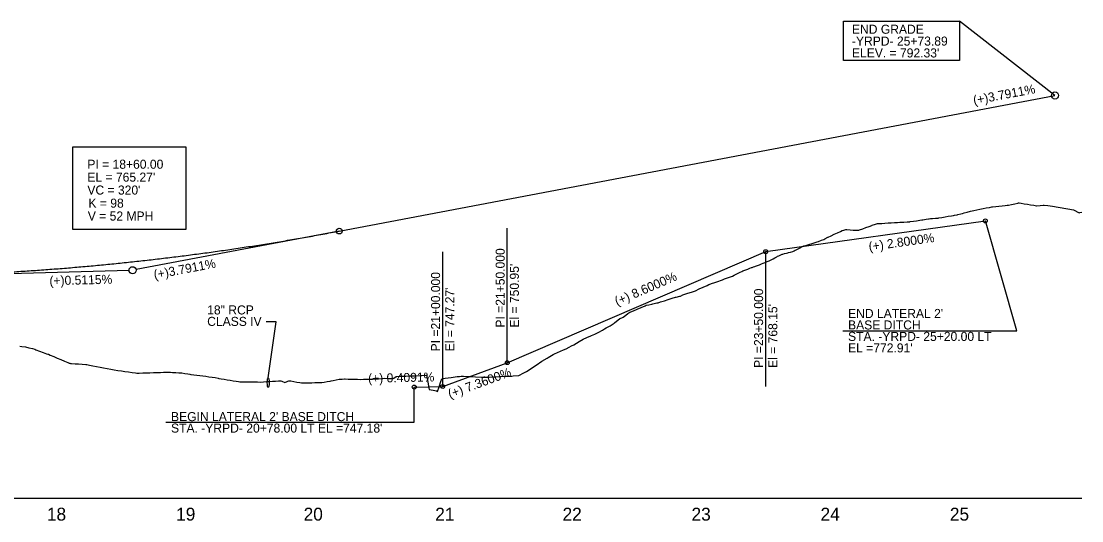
# Model space of a CAD drawing. Extents: x 579185 to 595036, y -53221 to -44640.
# Drawn here: x 580065 to 580886, y -53221 to -52834 of the extents above; entities that cross this region are included whole.
import ezdxf

# ---------------------------------------------------------------- set-up
doc = ezdxf.new("R2010")
doc.units = 0
for name, color, linetype in [('Exist Profile Cell', 7, 'Continuous'), ('Exist Vertical Profile Ground Line', 7, 'Continuous'), ('Exist Vertical Profile Horizontal Axis Label Major', 7, 'Continuous'), ('Prop Grid Mask', 7, 'Continuous'), ('Prop PFL Cross Pipe CELL', 7, 'Continuous'), ('Prop Vertical Profile Curve Label', 7, 'Continuous'), ('Prop Vertical Profile Ditch Grade Left', 7, 'Continuous'), ('Prop Vertical Profile Ditch Grade Left Label', 7, 'Continuous'), ('Prop Vertical Profile Ditch Grade Right Label', 7, 'Continuous'), ('Prop Vertical Profile Grade', 7, 'Continuous'), ('Prop Vertical Profile Grade Label', 7, 'Continuous'), ('Prop VPI Ditch Grade Left Label', 7, 'Continuous'), ('Prop VPI Label', 7, 'Continuous')]:
    doc.layers.add(name, color=color, linetype=linetype)

msp = doc.modelspace()

# ---------------------------------------------------------------- linework, layer by layer
at = {"layer": 'Exist Profile Cell'}
msp.add_line((579291.19, -53202.97), (580885.83, -53202.97), dxfattribs=at)
at = {"layer": 'Exist Vertical Profile Ground Line'}
for points in [[(580816.81, -52977.45), (580819.22, -52977.21), (580821.67, -52976.96), (580824.12, -52976.72), (580826.57, -52976.49), (580828.1, -52976.34), (580829.02, -52976.14), (580831.48, -52975.61), (580833.93, -52975.09), (580836.38, -52974.57), (580836.95, -52974.44), (580837.3, -52974.46), (580838.83, -52974.71), (580841.28, -52975.1), (580843.73, -52975.51), (580846.18, -52975.91), (580848.63, -52976.32), (580850.7, -52976.66), (580851.08, -52976.63), (580853.53, -52976.45), (580855.98, -52976.27), (580856.59, -52976.23), (580859.66, -52976.5), (580863.28, -52977.1), (580879.48, -52979.73), (580883.81, -52982.05), (580884.29, -52982.01), (580885.83, -52981.76)], [(580643.83, -53019.26), (580645.33, -53018.63), (580647.08, -53017.91), (580648.33, -53017.11), (580649.83, -53016.16), (580650.38, -53015.81), (580651.38, -53015.35), (580652.83, -53014.69), (580653.82, -53014.23), (580654.33, -53014.1), (580655.83, -53013.71), (580657.33, -53013.33), (580658.21, -53013.1), (580658.83, -53012.96), (580660.33, -53012.6), (580662.12, -53012.17), (580663.33, -53011.6), (580664.13, -53011.21), (580664.83, -53010.85), (580667.28, -53009.59), (580669.73, -53008.32), (580670.65, -53007.85), (580672.18, -53007.38), (580674.63, -53006.62), (580677.08, -53005.87), (580679.53, -53005.12), (580681.09, -53004.65), (580681.98, -53004.32), (580684.43, -53003.41), (580686.08, -53002.8), (580686.88, -53002.37), (580689.33, -53001.09), (580689.65, -53000.92), (580691.79, -52999.94), (580694.24, -52998.81), (580696.69, -52997.68), (580699.14, -52996.56), (580700.39, -52995.98), (580701.59, -52995.58), (580703.15, -52995.05), (580704.04, -52995.12), (580706.49, -52995.31), (580708.94, -52995.5), (580710.88, -52995.65), (580711.39, -52995.62), (580713.36, -52995.52), (580713.84, -52995.34), (580716.29, -52994.45), (580718.74, -52993.56), (580721.19, -52992.67), (580723.23, -52991.93), (580723.64, -52991.8), (580726.1, -52991.01), (580727.84, -52990.44), (580728.55, -52990.41), (580731, -52990.31), (580733.45, -52990.2), (580735.9, -52990.04), (580738.35, -52989.88), (580740.8, -52989.72), (580743.25, -52989.57), (580744.95, -52989.46), (580745.7, -52989.43), (580748.15, -52989.31), (580750.6, -52989.2), (580752.73, -52989.06), (580753.05, -52989.01), (580755.5, -52988.65), (580757.95, -52988.29), (580760.41, -52987.93), (580762.13, -52987.68), (580762.86, -52987.56), (580765.31, -52987.16), (580767.26, -52986.85), (580767.76, -52986.77), (580768.8, -52986.61), (580770.21, -52986.51), (580772.66, -52986.35), (580774.62, -52986.21), (580775.11, -52986.13), (580777.56, -52985.7), (580780.01, -52985.27), (580782.46, -52984.84), (580784.91, -52984.41), (580786.62, -52984.12), (580787.36, -52983.98), (580789.35, -52983.62), (580789.81, -52983.5), (580792.26, -52982.88), (580793.4, -52982.59), (580794.72, -52982.26), (580797.17, -52981.63), (580799.62, -52981.01), (580802.33, -52980.32), (580804.67, -52979.86), (580806.97, -52979.39), (580809.42, -52978.9), (580811.87, -52978.41), (580814.32, -52977.92), (580816.23, -52977.54), (580816.81, -52977.45)], [(580440.02, -53108.73), (580444.7, -53108.53), (580445.63, -53108.49), (580450.26, -53108), (580454.08, -53105.99), (580456.02, -53104.96), (580463.45, -53100.12), (580468.06, -53097.11), (580471.94, -53094.73), (580472.83, -53094.22), (580476.8, -53091.92), (580477.67, -53091.37), (580484.83, -53088.27), (580486.74, -53087.44), (580489.12, -53086.1), (580490.83, -53085.26), (580492.6, -53084.39), (580496.83, -53081.8), (580499.81, -53079.98), (580502.83, -53078.69), (580505.83, -53077.41), (580506.29, -53077.21), (580508.83, -53076.09), (580512.07, -53074.66), (580514.83, -53072.95), (580516.4, -53071.98), (580517.83, -53071.2), (580520.83, -53069.54), (580523.83, -53067.53), (580524.48, -53067.1), (580526.83, -53065.21), (580528.34, -53063.99), (580529.83, -53063.45), (580530.86, -53063.07), (580532.83, -53061.49), (580534.6, -53060.08), (580535.35, -53059.55), (580535.97, -53059.2), (580536.81, -53058.79), (580538.83, -53057.93), (580541.83, -53056.66), (580544.83, -53055.39), (580547.83, -53054.13), (580548.79, -53053.72), (580550.83, -53053.29), (580552.96, -53052.84), (580553.83, -53052.65), (580556.83, -53051.98), (580557.85, -53051.75), (580559.83, -53051.13), (580562.83, -53050.18), (580565.83, -53049.24), (580568.83, -53048.31), (580571.37, -53047.51), (580571.83, -53047.41), (580574.83, -53046.76), (580575.23, -53046.67), (580576.94, -53045.77), (580577.83, -53045.48), (580580.83, -53044.5), (580583.83, -53043.53), (580586.83, -53042.52), (580589.83, -53041.12), (580592.83, -53039.72), (580595.83, -53038.33), (580597.11, -53037.74), (580598.83, -53037.15), (580599.32, -53036.98), (580601.83, -53036.1), (580603.33, -53035.56), (580604.99, -53034.98), (580606.33, -53034.48), (580607.83, -53033.93), (580609.33, -53033.38), (580610.83, -53032.83), (580612.33, -53032.28), (580613.83, -53031.73), (580615.43, -53031.15), (580616.83, -53030.42), (580617.82, -53029.9), (580618.33, -53029.66), (580619.83, -53028.94), (580621.33, -53028.22), (580622.83, -53027.5), (580623.45, -53027.21), (580624.33, -53026.86), (580625.83, -53026.28), (580627.33, -53025.69), (580628.83, -53025.11), (580630.33, -53024.53), (580630.68, -53024.39), (580631.83, -53023.99), (580632.73, -53023.68), (580633.33, -53023.49), (580634.96, -53022.97), (580636.33, -53022.39), (580637.83, -53021.77), (580639.33, -53021.14), (580640.83, -53020.51), (580642.33, -53019.88), (580643.83, -53019.26)], [(580064.04, -53085.36), (580065.38, -53085.54), (580068.32, -53085.94), (580070.89, -53086.61), (580073.64, -53087.32), (580075.56, -53087.82), (580076.4, -53088.14), (580079.15, -53089.19), (580081.91, -53090.26), (580084.66, -53091.32), (580085.55, -53091.66), (580086.03, -53091.71), (580087.42, -53092.3), (580090.17, -53093.48), (580092.93, -53094.66), (580095.68, -53095.84), (580098.44, -53096.98), (580101.19, -53098.12), (580102.18, -53098.52), (580102.65, -53098.56), (580103.15, -53098.71), (580103.95, -53098.77), (580106.7, -53098.96), (580109.46, -53099.16), (580112.22, -53099.37), (580114.97, -53099.57), (580115.67, -53099.63), (580117.73, -53100.02), (580120.48, -53100.56), (580123.24, -53101.1), (580125.99, -53101.64), (580128.75, -53102.19), (580131.5, -53102.74), (580134.26, -53103.29), (580135.63, -53103.56), (580137.01, -53103.76), (580139.77, -53104.16), (580142.52, -53104.56), (580145.28, -53104.96), (580148.03, -53105.36), (580150.79, -53105.76), (580153.54, -53106.17), (580154.36, -53106.29), (580156.3, -53106.23), (580159.05, -53106.14), (580161.81, -53106.05), (580164.56, -53105.96), (580167.32, -53105.88), (580170.07, -53105.79), (580172.83, -53105.71), (580175.17, -53105.65), (580177.52, -53105.58), (580178.37, -53105.56), (580179.03, -53105.55), (580179.86, -53105.57), (580180.45, -53105.58), (580182.2, -53105.69), (580184.55, -53105.83), (580186.89, -53105.98), (580188.59, -53106.08), (580189.23, -53106.18), (580191.58, -53106.54), (580193.92, -53106.89), (580195.52, -53107.13), (580196.27, -53107.23), (580198.61, -53107.52), (580200.95, -53107.82), (580203.3, -53108.12), (580205.64, -53108.42), (580207.98, -53108.72), (580210.33, -53109.02), (580212.67, -53109.32), (580215.02, -53109.78), (580217.36, -53110.24), (580217.96, -53110.36), (580219.7, -53110.63), (580222.05, -53111), (580224.39, -53111.38), (580226.73, -53111.75), (580229.08, -53112.12), (580231.42, -53112.49), (580233.22, -53112.78), (580234.11, -53112.93), (580234.65, -53112.91), (580236.11, -53112.93)], [(580236.11, -53112.93), (580238.45, -53112.97), (580240.8, -53113), (580243.14, -53113.04), (580245.48, -53113.08), (580247.83, -53113.12), (580250.17, -53113.15), (580252.52, -53113.01), (580254.86, -53112.86), (580257.2, -53112.72), (580259.55, -53112.58), (580261.89, -53112.44), (580264.23, -53112.3), (580265.81, -53112.2), (580266.58, -53112.51), (580268.93, -53113.45), (580270.9, -53112.81), (580271.27, -53112.62), (580272.02, -53112.23), (580272.97, -53112.17), (580273.61, -53112.29), (580275.95, -53112.75), (580278.3, -53113.21), (580280.64, -53113.66), (580281.92, -53113.91), (580282.98, -53113.9), (580283.67, -53113.9), (580285.33, -53113.84), (580287.67, -53113.76), (580290.02, -53113.68), (580292.36, -53113.61), (580294.7, -53113.53), (580297.05, -53113.45), (580297.64, -53113.43), (580299.39, -53113.16), (580301.73, -53112.8), (580304.08, -53112.44), (580305.01, -53112.3), (580306.42, -53112), (580308.77, -53111.51), (580311.11, -53111.04), (580313.45, -53110.88), (580315.15, -53110.77), (580315.8, -53110.79), (580318.14, -53110.85), (580320.48, -53110.91), (580322.83, -53110.97), (580325.17, -53111.03), (580327.52, -53111.09), (580329.86, -53111.03), (580332.2, -53110.97), (580334.55, -53110.91), (580336.89, -53110.85), (580339.23, -53110.79), (580340.84, -53110.75), (580341.58, -53110.68), (580343.92, -53110.47), (580346.33, -53110.26), (580348.61, -53110.34), (580350.95, -53110.42), (580352.97, -53110.5), (580353.3, -53110.25), (580355.18, -53108.85), (580355.64, -53108.83), (580357.98, -53108.74), (580360.33, -53108.66), (580362.67, -53108.57), (580365.02, -53108.48), (580367.36, -53108.4), (580369.7, -53108.31), (580374.39, -53108.14), (580375.05, -53108.11), (580378.15, -53107.92), (580378.61, -53107.97), (580379.08, -53110.37), (580380.75, -53118.93), (580383.77, -53119.54), (580386.51, -53120.1), (580387.31, -53120.38), (580388.45, -53116.91), (580389.84, -53112.71), (580390.61, -53110.61), (580393.14, -53110.26), (580397.83, -53109.63), (580402.52, -53109), (580404.11, -53108.78), (580405.58, -53108.51), (580405.92, -53108.67), (580406.47, -53108.69), (580407.2, -53108.72), (580411.89, -53108.91), (580416.58, -53109.1), (580421.27, -53109.29), (580425.95, -53109.48), (580426.32, -53109.49), (580427.08, -53109.4), (580430.64, -53109.26), (580432.33, -53109.19), (580435.33, -53108.96), (580436.15, -53108.9), (580440.02, -53108.73)]]:
    msp.add_lwpolyline(points, dxfattribs=at)
at = {"layer": 'Prop Grid Mask'}
for points in [[(580701.37, -52833.82), (580791.11, -52833.82), (580791.11, -52864.21), (580701.37, -52864.21)], [(580104.99, -52931.02), (580192.35, -52931.02), (580192.35, -52995.2), (580104.99, -52995.2)]]:
    msp.add_lwpolyline(points, close=True, dxfattribs=at)
at = {"layer": 'Prop PFL Cross Pipe CELL'}
msp.add_ellipse((580256.19, -53113.62), major_axis=(0, 3.75), ratio=0.2, dxfattribs=at)
at = {"layer": 'Prop Vertical Profile Curve Label'}
msp.add_line((580865.08, -52891.3), (580791.11, -52833.82), dxfattribs=at)
msp.add_circle((580311.19, -52996.29), 2.25, dxfattribs=at)
at = {"layer": 'Prop Vertical Profile Ditch Grade Left'}
msp.add_lwpolyline([(580369.19, -53117.07), (580391.19, -53116.62), (580441.19, -53098.22), (580641.19, -53012.22), (580811.19, -52988.42)], dxfattribs=at)
at = {"layer": 'Prop Vertical Profile Ditch Grade Left Label'}
for p, q in [((580835.48, -53073.53), (580811.19, -52988.42)), ((580441.19, -53098.22), (580441.19, -52993.92)), ((580391.19, -53116.62), (580391.19, -53012.32)), ((580641.19, -53116.51), (580641.19, -53012.22)), ((580700.96, -53073.53), (580835.48, -53073.53)), ((580369.19, -53144.28), (580369.19, -53117.07)), ((580176.86, -53144.28), (580369.19, -53144.28))]:
    msp.add_line(p, q, dxfattribs=at)
for centre in [(580811.19, -52988.42), (580641.19, -53012.22), (580441.19, -53098.22), (580369.19, -53117.07), (580391.19, -53116.62)]:
    msp.add_circle(centre, 1.5, dxfattribs=at)
at = {"layer": 'Prop Vertical Profile Ditch Grade Right Label'}
for p, q in [((580262.29, -53066.62), (580254.62, -53066.62)), ((580256.19, -53109.87), (580262.29, -53066.62))]:
    msp.add_line(p, q, dxfattribs=at)
at = {"layer": 'Prop Vertical Profile Grade'}
msp.add_line((580311.19, -52996.29), (580865.08, -52891.3), dxfattribs=at)
msp.add_spline([(579991.19, -53030.71), (579997.59, -53030.54), (580003.99, -53030.34), (580010.39, -53030.13), (580016.79, -53029.89), (580023.19, -53029.63), (580029.59, -53029.35), (580035.99, -53029.05), (580042.39, -53028.73), (580048.79, -53028.39), (580055.19, -53028.03), (580061.59, -53027.64), (580067.99, -53027.24), (580074.39, -53026.81), (580080.79, -53026.36), (580087.19, -53025.9), (580093.59, -53025.41), (580099.99, -53024.9), (580106.39, -53024.37), (580112.79, -53023.81), (580119.19, -53023.24), (580125.59, -53022.65), (580131.99, -53022.03), (580138.39, -53021.4), (580144.79, -53020.74), (580151.19, -53020.06), (580157.59, -53019.36), (580163.99, -53018.64), (580170.39, -53017.9), (580176.79, -53017.14), (580183.19, -53016.36), (580189.59, -53015.55), (580195.99, -53014.73), (580202.39, -53013.88), (580208.79, -53013.02), (580215.19, -53012.13), (580221.59, -53011.22), (580227.99, -53010.29), (580234.39, -53009.34), (580240.79, -53008.37), (580247.19, -53007.37), (580253.59, -53006.36), (580259.99, -53005.33), (580266.39, -53004.27), (580272.79, -53003.19), (580279.19, -53002.09), (580285.59, -53000.98), (580291.99, -52999.84), (580298.39, -52998.68), (580304.79, -52997.49), (580311.19, -52996.29)], degree=3, dxfattribs=at)
at = {"layer": 'Prop VPI Label'}
for p, q in [((580311.19, -52996.29), (580153.9, -53026.11)), ((579991.19, -53030.71), (580148.44, -53026.69))]:
    msp.add_line(p, q, dxfattribs=at)
for centre in [(580865.08, -52891.3), (580151.19, -53026.62)]:
    msp.add_circle(centre, 2.75, dxfattribs=at)

# ---------------------------------------------------------------- texts
at = {"layer": 'Exist Vertical Profile Horizontal Axis Label Major'}
for s, p in [('18', (580084.86, -53220.47)), ('19', (580184.9, -53220.47)), ('20', (580283.58, -53220.47)), ('21', (580385.42, -53220.47)), ('22', (580483.97, -53220.47)), ('23', (580583.8, -53220.47)), ('24', (580683.64, -53220.47)), ('25', (580783.74, -53220.47))]:
    msp.add_text(s, height=10, dxfattribs=at).set_placement(p)
at = {"layer": 'Prop Vertical Profile Curve Label'}
for s, p in [("VC = 320'", (580116.19, -52968.04)), ('K = 98', (580117.02, -52978.18)), ('V = 52 MPH', (580116.53, -52988.14))]:
    msp.add_text(s, height=7, dxfattribs=at).set_placement(p)
at = {"layer": 'Prop Vertical Profile Ditch Grade Left Label'}
for s, rotation, p in [('(+) 2.8000%', 7.96961, (580721.36, -53011.8)), ('(+) 8.6000%', 23.2677, (580526.12, -53054.26)), ('(+) 0.4091%', 1.1718, (580333.56, -53113.77)), ('(+) 7.3600%', 20.20362, (580396.83, -53126.03))]:
    msp.add_text(s, height=7, rotation=rotation, dxfattribs=at).set_placement(p)
for s, p in [("END LATERAL 2'", (580704.94, -53063.6)), ('BASE DITCH', (580704.94, -53072.48)), ('STA. -YRPD- 25+20.00 LT ', (580704.94, -53081.35)), ("EL =772.91'", (580704.94, -53090.23)), ("BEGIN LATERAL 2' BASE DITCH", (580180.95, -53143.45)), ("STA. -YRPD- 20+78.00 LT EL =747.18'", (580180.95, -53152.32))]:
    msp.add_text(s, height=7, dxfattribs=at).set_placement(p)
at = {"layer": 'Prop Vertical Profile Ditch Grade Right Label'}
for s, p in [('18" RCP', (580208.94, -53060.85)), ('CLASS IV', (580208.94, -53069.73))]:
    msp.add_text(s, height=7, dxfattribs=at).set_placement(p)
at = {"layer": 'Prop Vertical Profile Grade Label'}
for s, rotation, p in [('(+)3.7911%', 10.73325, (580802.47, -52898.53)), ('(+)3.7911%', 10.73325, (580168.24, -53033.57)), ('(+)0.5115%', 1.46492, (580086.93, -53038.27))]:
    msp.add_text(s, height=7, rotation=rotation, dxfattribs=at).set_placement(p)
at = {"layer": 'Prop VPI Ditch Grade Left Label'}
for s, p in [('PI =21+50.000', (580439.19, -53071.03)), ("El = 750.95'", (580450.19, -53071.03)), ('PI =21+00.000', (580389.19, -53089.43)), ("El = 747.27'", (580400.19, -53089.43)), ('PI =23+50.000', (580639.19, -53102.22)), ("El = 768.15'", (580650.19, -53102.22))]:
    msp.add_text(s, height=7, rotation=90, dxfattribs=at).set_placement(p)
at = {"layer": 'Prop VPI Label'}
for s, p in [('END GRADE', (580707.93, -52843.53)), ('-YRPD- 25+73.89', (580707.93, -52852.71)), ("ELEV. = 792.33'", (580707.93, -52861.88)), ('PI = 18+60.00', (580116.19, -52948.04)), ("EL = 765.27'", (580116.19, -52958.04))]:
    msp.add_text(s, height=7, dxfattribs=at).set_placement(p)

doc.saveas('drawing.dxf')
